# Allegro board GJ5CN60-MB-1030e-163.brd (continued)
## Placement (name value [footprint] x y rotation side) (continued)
C1069  -  [M-C0402]  43 104.73 270 bottom
C1070  -  [M-C0402]  42.37 90.12 0 top
C1071  -  [M-C0402]  56.34 140.16 90 bottom
C1072  -  [M-C0603]  45.87 72.65 180 bottom
C1073  -  [M-C0603]  46.58 74.73 180 bottom
C1074  -  [M-C0402]  35.89 90.12 180 top
C1075  -  [M-C0402]  33.98 90.12 180 top
C1076  -  [M-C0402]  29.16 98.25 270 top
C1077  -  [M-C0402]  29.16 100.16 270 top
C1078  -  [M-C0603]  28.9 102.57 90 top
C1128  -  [M-C0402]  72.47 104.22 180 bottom
C1137  -  [M-C0402]  76.4 101.43 180 bottom
C1138  -  [M-C0603]  83.98 98.66 90 bottom
C1139  -  [M-C0603]  22.94 85.55 0 bottom
C1144  -  [M-C0603]  81.21 98.66 90 bottom
C1151  -  [M-C0402]  70.69 104.22 180 bottom
C1152  -  [M-C0402]  70.69 102.82 180 bottom
C1153  -  [M-C0402]  96.67 96.83 180 bottom
C1161  -  [M-C0603]  78.24 98.61 90 bottom
C1163  -  [M-C0603]  75.44 98.59 270 bottom
C1164  -  [M-C0402]  72.47 101.43 180 bottom
C1165  -  [M-C0603]  22.94 86.95 0 bottom
C1167  -  [M-C0603]  73.95 98.66 90 bottom
C1169  -  [M-C0603]  82.61 98.59 270 bottom
C1170  -  [M-C0402]  183.69 153.11 0 top
C1176  -  [M-C0402]  126.47 156.11 90 top
C1179  -  [M-C0402]  18.87 147.53 180 top
C1180  -  [M-C0402]  18.87 149.05 180 top
C1181  -  [M-C0402]  87.07 113.36 0 bottom
C1182  -  [M-C0402]  76.4 102.82 180 bottom
C1183  -  [M-C0402]  79.7 105.62 180 bottom
C1184  -  [M-C0402]  86.82 106 90 bottom
C1185  -  [M-C0402]  18.11 122.51 180 top
C1186  -  [M-C0402]  70.69 101.43 180 bottom
C1187  -  [M-C0402]  97.66 111.59 90 bottom
C1188  -  [M-C0402]  72.47 102.82 180 bottom
C1189  -  [M-C0402]  74.04 89.61 0 bottom
C1190  -  [M-C0402]  92.4 110.06 90 bottom
C1191  -  [M-C0402]  82.12 95.84 180 bottom
C1192  -  [M-C0402]  85.93 95.84 0 bottom
C1193  -  [M-C0402]  117.68 156.04 90 top
C1194  -  [M-C0402]  133.88 155.5 90 top
C1195  -  [M-C0402]  141.83 156.01 90 top
C1196  -  [M-C0402]  152.12 150.78 90 top
C1197  -  [M-C0402]  161.11 150.78 90 top
C1216  -  [M-C0402]  133.06 155.37 90 top
C1217  -  [M-C0402]  140.56 155.37 90 top
C1218  -  [M-C0402]  87.73 93.69 0 bottom
C1219  -  [M-C0402]  148.77 155.5 90 top
C1220  -  [M-C0402]  125.34 155.58 90 top
C1221  -  [M-C0402]  159.46 150.24 90 top
C1222  -  [M-C0402]  168.6 150.32 90 top
C1223  -  [M-C0402]  105.99 101.43 180 bottom
C1224  -  [M-C0402]  105.99 98.25 180 bottom
C1225  -  [M-C0402]  108.03 100.28 180 bottom
C1226  -  [M-C0402]  108.03 99.39 180 bottom
C1227  -  [M-C0402]  105.99 99.14 180 bottom
C1234  -  [M-C0603]  16.71 61.67 90 top
C1235  -  [M-C0603]  32.07 57.18 0 top
C1236  -  [M-C0603]  184.76 112.33 90 top
C1237  -  [M-C0603]  185.04 103.94 270 top
C1243  -  [M-C0402]  87.72 89.39 180 bottom
C1244  -  [M-C0402]  68.43 94.87 90 bottom
C1245  -  [M-C0603]  73.98 95.08 270 bottom
C1246  -  [M-C0402]  80.09 95.84 0 bottom
C1247  -  [M-C0603]  5.41 72.09 0 top
C1248  -  [M-C0402]  85.93 93.04 0 bottom
C1249  -  [M-C0402]  84.15 93.04 0 bottom
C1250  -  [M-C0603]  75.43 95.08 270 bottom
C1251  -  [M-C0603]  96.21 111.59 90 bottom
C1252  -  [M-C0402]  78.05 89.61 180 bottom
C1253  -  [M-C0603]  93.92 111.59 90 bottom
C1254  -  [M-C0603]  91.26 109.81 90 bottom
C1255  -  [M-C0603]  89.91 107.67 90 bottom
C1256  -  [M-C0603]  41.86 143.46 180 bottom
C1257  -  [M-C0603]  72.57 98.59 270 bottom
C1258  -  [M-C0603]  3 68.41 90 top
C1259  -  [M-C0603]  5.16 65.1 180 top
C1260  -  [M-C0402]  94.06 113.36 180 bottom
C1261  -  [M-C0402]  81.72 91.63 0 bottom
C1262  -  [M-C0402]  82.12 93.04 180 bottom
C1263  -  [M-C0402]  96.21 113.36 0 bottom
C1264  -  [M-C0402]  80.96 107.66 180 bottom
C1265  -  [M-C0402]  82.74 107.66 0 bottom
C1266  -  [M-C0402]  77.93 105.62 0 bottom
C1267  -  [M-C0402]  70.05 105.62 0 bottom
C1268  -  [M-C0603]  76.77 98.66 90 bottom
C1269  -  [M-C0603]  88.87 112.73 270 bottom
C1270  -  [M-C0603]  183.59 8.72 0 top
C1271  -  [M-C0603]  183.59 7.32 0 top
C1272  -  [M-C0603]  178.76 9.6 180 top
C1273  -  [M-C0603]  81.19 102.17 90 bottom
C1274  -  [M-C0402]  85.07 89.58 180 bottom
C1275  -  [M-C0603]  41.86 136.35 180 bottom
C1276  -  [M-C0603]  188.29 18.88 0 bottom
C1277  -  [M-C0402]  81.23 104.22 0 bottom
C1278  -  [M-C0603]  188.29 20.27 0 bottom
C1279  -  [M-C0402]  71.83 105.62 0 bottom
C1280  -  [M-C0603]  188.29 17.48 0 bottom
C1281  -  [M-C0402]  85.55 105.62 180 bottom
C1282  -  [M-C0402]  68.77 101.55 180 bottom
C1283  -  [M-C0402]  69.42 107.65 0 bottom
C1284  -  [M-C0402]  75.89 107.65 0 bottom
C1285  -  [M-C0402]  86.31 91.65 180 bottom
C1286  -  [M-C0603]  70.61 98.59 90 bottom
C1287  -  [M-C0402]  68.91 102.71 180 bottom
C1288  -  [M-C0603]  79.82 98.59 270 bottom
C1289  -  [M-C0402]  83.64 105.62 180 bottom
C1290  -  [M-C0402]  9.98 88.73 270 bottom
C1291  -  [M-C0402]  75.89 105.62 0 bottom
C1292  -  [M-C0402]  70.15 91.6 0 bottom
C1293  -  [M-C0402]  129.44 159.52 0 top
C1294  -  [M-C0402]  136.75 159.01 0 top
C1295  -  [M-C0402]  89.51 96.98 270 bottom
C1296  -  [M-C0402]  90.24 100.67 0 bottom
C1297  -  [M-C0603]  4.16 88.6 270 bottom
C1298  -  [M-C0402]  76.4 91.65 180 bottom
C1299  -  [M-C0402]  73.71 91.6 180 bottom
C1300  -  [M-C0402]  144.91 159.46 0 top
C1301  -  [M-C0402]  121.23 159.46 0 top
C1302  -  [M-C0402]  90.25 98.68 0 bottom
C1303  -  [M-C0402]  86.35 89.16 90 bottom
C1304  -  [M-C0603]  2.74 88.6 270 bottom
C1305  -  [M-C0603]  8.71 88.6 270 bottom
C1306  -  [M-C0603]  7.06 88.57 270 bottom
C1307  -  [M-C0402]  162.13 154.56 180 top
C1308  -  [M-C0402]  155.27 154.13 0 top
C1309  -  [M-C0603]  66.24 86.95 45 bottom
C1310  -  [M-C0402]  6.93 154.89 270 top
C1311  -  [M-C0402]  6.88 141.18 90 top
C1312  -  [M-C0402]  17.98 129.49 270 bottom
C1313  -  [M-C0402]  74.12 105.62 0 bottom
C1314  -  [M-C0402]  128.85 154.26 0 top
C1315  -  [M-C0402]  193.83 98 0 top
C1316  -  [M-C0402]  136.22 153.75 0 top
C1317  -  [M-C0402]  144.35 154 0 top
C1318  -  [M-C0402]  140.54 28.15 90 top
C1319  -  [M-C0603]  139.39 27.89 90 top
C1320  -  [M-C0603]  85.29 109.73 180 bottom
C1321  -  [M-C0402]  159.46 28.65 90 top
C1322  -  [M-C0402]  158.57 28.65 90 top
C1323  -  [M-C0402]  120.6 154.13 0 top
C1324  -  [M-C0402]  154.76 148.67 0 top
C1325  -  [M-C0402]  163.52 148.67 0 top
C1326  -  [M-C0402]  164.29 28.15 90 top
C1327  -  [M-C0603]  165.43 27.89 90 top
C1328  -  [M-C0402]  180.8 28.02 90 top
C1329  -  [M-C0402]  179.91 28.02 90 top
C1330  -  [M-C0402]  80.09 94.44 0 bottom
C1331  -  [M-C0402]  75.25 92.92 180 bottom
C1332  -  [M-C0402]  84.15 94.44 0 bottom
C1333  -  [M-C0402]  73.47 92.92 180 bottom
C1334  -  [M-C0402]  74.24 101.43 0 bottom
C1335  -  [M-C0402]  82.12 94.44 180 bottom
C1336  -  [M-C0402]  81.48 105.62 0 bottom
C1337  -  [M-C0402]  84.15 95.84 0 bottom
C1338  -  [M-C0402]  85.93 94.44 0 bottom
C1339  -  [M-C0402]  79.99 91.61 0 bottom
C1340  -  [M-C0402]  79.87 89.62 0 bottom
C1341  -  [M-C0402]  70.31 89.61 0 bottom
C1342  -  [M-C0402]  83.77 91.65 180 bottom
C1343  -  [M-C0603]  67.77 109.05 135 bottom
C1344  -  [M-C0603]  22.88 84.23 0 bottom
C1345  -  [M-C0603]  22.91 82.86 0 bottom
C1346  -  [M-C0603]  80.52 85.3 180 bottom
C1347  -  [M-C0402]  67.44 159.85 90 top
C1348  -  [M-C0603]  89.1 122 180 bottom
C1349  -  [M-C0402]  183.64 69.22 0 bottom
C1350  -  [M-C0603]  28.9 84.99 270 top
C1351  -  [M-C0603]  26.24 93.68 90 top
C1352  -  [M-C0603]  23.44 93.68 90 top
C1353  -  [M-C0603]  24.84 93.68 90 top
C1354  -  [M-C0603]  40.97 67.14 0 bottom
C1355  -  [M-C0603]  87.96 106 270 bottom
C1356  -  [M-C0603]  86.05 98.66 90 bottom
C1357  -  [M-C0603]  40.97 68.66 0 bottom
C1358  -  [M-C0603]  178.76 9.6 180 bottom
C1361  -  [M-C0402]  19.89 74.25 270 bottom
C1362  -  [M-C0402]  19.86 120.09 270 top
C1363  -  [M-C0603]  2.23 79.71 180 bottom
C1364  -  [M-C0402]  20.27 67.64 180 bottom
C1367  -  [M-C0402]  13.16 65.03 180 top
C1368  -  [M-C0402]  24.33 105.49 0 top
C1369  -  [M-C0805]  84.02 53.42 270 top
C1370  -  [M-C0603]  83.39 72.09 180 top
C1371  -  [M-C0402]  13.79 105.11 0 top
C1372  -  [M-C0805]  161.87 137.21 0 top
C1373  -  [M-C0805]  161.87 135.18 0 top
C1374  -  [M-C0402]  93.04 62.06 180 top
C1375  -  [M-C0402]  79.7 55.32 180 top
C1376  -  [M-C0805]  152.35 137.87 180 top
C1377  -  [M-C0805]  152.35 135.84 180 top
C1378  -  [M-C0603]  5.61 88.6 270 bottom
C1382  -  [M-C0402]  74.12 107.65 0 bottom
C1383  -  [M-C0402]  76.4 104.22 180 bottom
C1384  -  [M-C0402]  83.01 104.22 0 bottom
C1385  -  [M-C0603]  2.23 81.11 180 bottom
C1386  -  [M-C0402]  74.24 104.22 0 bottom
C1387  -  [M-C0402]  75.38 89.11 270 bottom
C1388  -  [M-C0402]  77.21 108.08 90 bottom
C1389  -  [M-C0402]  74.24 102.82 0 bottom
C1390  -  [M-C0402]  78.17 91.63 180 bottom
C1391  -  [M-C0603]  92.15 128.73 90 bottom
C1392  -  [M-C0402]  68.81 96.19 180 bottom
C1393  -  [M-C0402]  71.96 108.08 90 bottom
C1394  -  [M-C0402]  78.03 108.06 270 bottom
C1395  -  [M-C0402]  80.96 108.55 180 bottom
C1396  -  [M-C0402]  84.15 108.03 270 bottom
C1397  -  [M-C0402]  70.43 88.73 0 bottom
C1398  -  [M-C0402]  72.85 108.08 90 bottom
C1399  -  [M-C0402]  74.12 108.54 180 bottom
C1400  -  [M-C0402]  76.27 89.11 270 bottom
C1401  -  [M-C0402]  95.07 111.33 90 bottom
C1402  -  [M-C0402]  71.93 91.6 0 bottom
C1403  -  [M-C0402]  68.66 104.47 0 bottom
C1404  -  [M-C0402]  81.17 89.14 270 bottom
C1405  -  [M-C0402]  68.85 103.58 180 bottom
C1406  -  [M-C0402]  68.66 93.55 180 bottom
C1407  -  [M-C0402]  68.91 97.92 180 bottom
C1408  -  [M-C0402]  78.87 108.06 90 bottom
C1409  -  [M-C0402]  71.83 89.13 270 bottom
C1410  -  [M-C0402]  68.81 98.78 0 bottom
C1411  -  [M-C0402]  68.81 97.06 180 bottom
C1412  -  [M-C0402]  68.77 100.66 180 bottom
C1413  -  [M-C0402]  88.09 88.09 90 bottom
C1414  -  [M-C0603]  6.04 79.33 270 bottom
C1415  -  [M-C0402]  86.69 86.82 90 bottom
C1416  -  [M-C0402]  79.87 88.73 0 bottom
C1417  -  [M-C0402]  87.83 99.67 0 bottom
C1418  -  [M-C0402]  99.77 83.77 90 top
C1419  -  [M-C0402]  99.77 85.68 270 top
C1420  -  [M-C7343]  82.06 102.65 180 bottom
C1421  -  [M-C0402]  75.89 108.54 0 bottom
C1422  -  [M-C0402]  79.7 108.05 90 bottom
C1423  -  [M-C0603]  61.34 57.99 0 top
C1424  -  [M-C7343]  74.46 94.63 0 bottom
C1425  -  [M-C0603]  68.58 58.25 270 top
C1426  -  [M-C0402]  82.63 58.75 180 top
C1427  -  [M-C0402]  72.97 47.7 90 top
C1428  -  [M-C7343]  42.37 68.15 0 top
C1429  -  [M-C0603]  7.44 79.33 270 bottom
C1431  -  [M-C0603]  22.94 78.06 0 bottom
C1432  -  [M-C0402]  71.07 108.08 90 bottom
C1433  -  [M-C0402]  87.75 96.53 0 bottom
C1434  -  [M-C0603]  2.11 79.71 180 top
C1435  -  [M-C7343]  38.05 159.72 90 top
C1436  -  [M-C7343]  33.5 159.69 90 top
C1437  -  [M-C7343]  26.11 76.15 90 top
C1438  -  [M-C0805]  83.26 70.31 180 top
C1439  -  [M-C7343]  31.06 138.59 180 bottom
C1440  -  [M-C0603]  69.59 62.94 90 top
C1441  -  [M-C0603]  67.18 58.25 270 top
C1442  -  [M-C0402]  90.4 87.76 90 bottom
C1443  -  [M-C0402]  89.51 87.76 90 bottom
C1444  -  [M-C0402]  77.67 88.73 0 bottom
C1445  -  [M-C0402]  84.4 77.04 180 top
C1446  -  [M-C0402]  90.63 90.12 180 bottom
C1447  -  [M-C0603]  4.27 82.12 90 bottom
C1448  -  [M-C0603]  5.79 154.89 270 top
C1449  -  [M-C7343]  31.06 147.53 180 bottom
C1450  -  [M-C0603]  2.11 81.11 180 top
C1451  -  [M-C0402]  88.09 91.93 0 bottom
C1452  -  [M-C0402]  107.26 72.98 180 top
C1453  -  [M-C7343]  31.06 134.19 180 bottom
C1454  -  [M-C0603]  2.36 140.54 180 top
C1455  -  [M-C0603]  4.32 141.13 90 top
C1456  -  [M-C0402]  87.71 92.79 0 bottom
C1457  -  [M-C0402]  87.75 97.42 0 bottom
C1458  -  [M-C0402]  87.83 90.25 0 bottom
C1459  -  [M-C7343]  31.06 143.08 180 bottom
C1463  -  [M-C0603]  5.74 141.18 90 top
C1464  -  [M-C0603]  12.62 161.37 90 top
C1465  -  [M-C0603]  14.05 161.37 90 top
C1466  -  [M-C0603]  15.47 161.37 90 top
C1467  -  [M-C0603]  16.84 129.24 270 bottom
C1468  -  [M-C0603]  6.04 127.84 180 top
C1469  -  [M-C7343]  25.35 134.83 180 top
C1470  -  [M-C0603]  11.23 161.37 90 top
C1471  -  [M-C0603]  2.36 139.14 180 top
C1472  -  [M-C0603]  4.14 158.83 180 top
C1476  -  [M-C0402]  113.24 124.03 180 top
C1477  -  [M-C0402]  115.15 122.99 180 top
C1478  -  [M-C0402]  113.23 121.95 180 top
C1479  -  [M-C0402]  115.14 120.91 180 top
C1480  -  [M-C0402]  113.22 119.78 180 top
C1481  -  [M-C0402]  115.14 118.75 180 top
C1482  -  [M-C0402]  113.23 117.68 180 top
C1483  -  [M-C0402]  115.14 116.64 180 top
C1488  -  [M-C0402]  113.23 114.71 180 top
C1489  -  [M-C0402]  115.14 114.51 180 top
C1490  -  [M-C0402]  113.23 113.49 180 top
C1491  -  [M-C0402]  115.14 112.4 180 top
C1492  -  [M-C0402]  113.23 123.14 180 top
C1493  -  [M-C0402]  115.15 122.1 180 top
C1494  -  [M-C0402]  113.23 121.06 180 top
C1495  -  [M-C0402]  115.14 120.02 180 top
C1496  -  [M-C0402]  113.22 118.92 180 top
C1497  -  [M-C0402]  115.14 117.86 180 top
C1498  -  [M-C0402]  113.23 116.79 180 top
C1499  -  [M-C0402]  115.14 115.75 180 top
C1504  -  [M-C0402]  113.23 115.6 180 top
C1505  -  [M-C0402]  115.14 113.62 180 top
C1506  -  [M-C0402]  113.23 112.6 180 top
C1507  -  [M-C0402]  115.14 111.51 180 top
C1508  -  [M-C0402]  175.98 12.69 0 top
C1509  -  [M-C0402]  113.23 110.44 180 top
C1510  -  [M-C0402]  113.23 111.33 180 top
C1511  -  [M-C0402]  115.14 109.43 180 top
C1512  -  [M-C0402]  115.14 110.32 180 top
C1513  -  [M-C0402]  113.23 109.15 180 top
C1514  -  [M-C0402]  113.23 108.26 180 top
C1515  -  [M-C0402]  115.14 107.29 180 top
C1516  -  [M-C0402]  115.14 108.18 180 top
C2396  -  [M-C0603]  6.04 129.24 180 top
C2397  -  [M-C0603]  15.44 129.24 270 bottom
C2398  -  [M-C0603]  4.14 157.43 180 top
C2549  -  [M-C0402]  23.57 111.08 270 top
C2550  -  [M-C0402]  20.01 111.08 90 top
C2551  -  [M-C0402]  16.84 72.22 270 top
C2552  -  [M-C0402]  24.08 109.68 180 top
C2553  -  [M-C0402]  21.64 109.68 180 top
C2554  -  [M-C0402]  14.98 70.69 270 bottom
C2555  -  [M-C0402]  16.33 69.17 0 bottom
C2575  -  [M-C0402]  78.05 157.31 270 bottom
C2578  -  [M-C0402]  69.8 156.8 180 bottom
C2579  -  [M-C0402]  69.8 155.53 180 bottom
C2745  -  [M-C0402]  170.51 12.91 90 top
C2746  -  [M-C0402]  112.09 5.54 90 bottom
C2747  -  [M-C0402]  98.12 4.78 90 bottom
C2821  -  [M-C0402]  18.36 108.92 270 top
C3384  -  [M-C0402]  167.69 24.18 90 top
C3399  -  [M-C0402]  111.45 88.73 270 bottom
C3401  -  [M-C0402]  113.49 76.79 0 bottom
C3416  -  [M-C0402]  124.79 75.52 0 bottom
C3417  -  [M-C0402]  140.92 68.28 90 bottom
C3418  -  [M-C0402]  142.32 68.28 90 bottom
C3419  -  [M-C0402]  146 68.28 90 bottom
C3420  -  [M-C0402]  147.01 68.28 90 bottom
C3421  -  [M-C0603]  118.06 80.85 90 bottom
C3422  -  [M-C0402]  141.43 81.49 90 bottom
C3423  -  [M-C0402]  151.21 77.04 0 bottom
C3424  -  [M-C0402]  115.14 80.98 90 bottom
C3425  -  [M-C0402]  151.84 68.28 90 bottom
C3426  -  [M-C0603]  110.31 88.98 270 bottom
C3427  -  [M-C0603]  141.68 91.77 90 top
C3428  -  [M-C0603]  146.13 91.77 90 top
C3431  -  [M-C0603]  152.35 91.77 90 top
C3432  -  [M-C0603]  144.52 91.77 90 top
C3438  -  [M-C0603]  145.74 77.04 180 bottom
C3439  -  [M-C0603]  169.75 76.28 90 bottom
C3440  -  [M-C0603]  154.38 77.04 0 bottom
C3441  -  [M-C0603]  125.04 76.79 0 bottom
C3443  -  [M-C0603]  118.69 67.52 90 bottom
C3445  -  [M-C0402]  117.55 67.9 90 bottom
C3447  -  [M-C0603]  113.11 68.66 180 bottom
C3463  -  [M-C0402]  162.64 91.9 270 top
C3464  -  [M-C0402]  173.3 91.9 270 top
C3465  -  [M-C0402]  154.12 91.76 270 top
C3466  -  [M-C0402]  127.18 90.99 0 top
C3467  -  [M-C0402]  138.51 92.03 270 top
C3468  -  [M-C0402]  140.03 92.03 270 top
C3470  -  [M-C0402]  149.05 91.77 90 top
C3471  -  [M-C0402]  143.18 91.9 90 top
C3491  -  [M-C0402]  80.01 6.58 90 top
C3493  -  [M-C0402]  80.9 6.61 90 top
C3495  -  [M-C0402]  97.36 7.57 0 top
C3496  -  [M-C0603]  96.85 8.21 0 bottom
C3532  -  [M-C0402]  63.14 36.33 0 top
C3535  -  [M-C0402]  63.58 34.98 90 top
C3536  -  [M-C0402]  62.66 34.95 270 top
C3537  -  [M-C0402]  69.93 39.2 180 top
C3538  -  [M-C0603]  6.02 39.53 270 top
C3539  -  [M-C0603]  45.16 62.31 90 bottom
C3540  -  [M-C0603]  3.15 39.6 270 top
C3541  -  [M-C0402]  60.65 40.59 0 top
C3543  -  [M-C0402]  52.91 56.98 0 top
C3544  -  [M-C0603]  45.03 52.66 0 bottom
C3545  -  [M-C0603]  16.84 45.29 90 top
C3546  -  [M-C0603]  45.03 54.05 0 bottom
C3547  -  [M-C0603]  45.03 51.23 0 bottom
C3548  -  [M-C0603]  27.38 42.12 0 top
C3549  -  [M-C0402]  39.95 39.58 270 bottom
C3550  -  [M-C0402]  43.13 39.58 270 bottom
C3551  -  [M-C0402]  28.02 38.05 270 top
C3552  -  [M-C0402]  37.79 39.58 270 bottom
C3553  -  [M-C0402]  41.22 39.58 270 bottom
C3554  -  [M-C0603]  4.57 39.58 270 top
C3556  -  [M-C0402]  65.28 36.27 180 top
C3557  -  [M-C0402]  69.93 40.08 180 top
C3558  -  [M-C0402]  27.13 45.67 0 top
C3559  -  [M-C0402]  61.54 46.82 0 top
C3560  -  [M-C0402]  66.75 46.18 90 top
C3561  -  [M-C0603]  183.46 99.14 90 top
C3562  -  [M-C0603]  184.86 99.14 90 top
C3563  -  [M-C0603]  186.26 99.14 90 top
C3564  -  [M-C0402]  15.19 45.42 90 top
C3565  -  [M-C0402]  69.93 41.23 180 top
C3566  -  [M-C0603]  192.1 69.68 0 top
C3567  -  [M-C0603]  192.1 71.2 0 top
C3568  -  [M-C0603]  192.1 74.25 0 top
C3569  -  [M-C0603]  192.1 72.72 0 top
C3570  -  [M-C0603]  188.29 16.08 0 bottom
C3571  -  [M-C0603]  129.56 160.66 0 top
C3572  -  [M-C0603]  59.89 39.45 0 top
C3573  -  [M-C0603]  46.56 62.31 270 bottom
C3574  -  [M-C0402]  63.58 45.04 180 top
C3575  -  [M-C0603]  40.33 44.4 0 bottom
C3576  -  [M-C0402]  61.04 44.53 90 top
C3577  -  [M-C0603]  40.33 45.93 0 bottom
C3578  -  [M-C0603]  41.48 172.16 0 top
C3579  -  [M-C0402]  60.65 42.37 180 top
C3580  -  [M-C0402]  61.92 44.53 90 top
C3581  -  [M-C0402]  51 62.06 270 top
C3582  -  [M-C0402]  69.16 35.89 180 top
C3583  -  [M-C0402]  67.77 37.67 90 top
C3584  -  [M-C0603]  129.56 162.11 0 bottom
C3585  -  [M-C0603]  129.56 163.53 0 top
C3586  -  [M-C0603]  129.56 162.11 0 top
C3587  -  [M-C0603]  129.56 163.53 0 bottom
C3588  -  [M-C0603]  136.93 160.23 0 top
C3589  -  [M-C0603]  136.93 161.65 0 top
C3590  -  [M-C0603]  136.93 160.23 0 bottom
C3591  -  [M-C0603]  136.93 161.65 0 bottom
C3592  -  [M-C0603]  136.93 163.05 0 top
C3593  -  [M-C0603]  182.07 99.14 90 top
C3594  -  [M-C0603]  145.08 160.63 0 top
C3595  -  [M-C0603]  145.08 162.06 0 top
C3596  -  [M-C0603]  145.08 163.48 0 top
C3597  -  [M-C0603]  145.08 160.63 0 bottom
C3598  -  [M-C0603]  145.08 162.06 0 bottom
C3599  -  [M-C0603]  121.36 160.61 0 bottom
C3600  -  [M-C0603]  83.9 42.5 270 top
C3601  -  [M-C0603]  82.5 42.5 270 top
C3602  -  [M-C0603]  81.1 42.5 270 top
C3603  -  [M-C0402]  91.52 41.23 180 top
C3604  -  [M-C0402]  85.55 47.32 270 top
C3605  -  [M-C0603]  121.36 162 0 bottom
C3606  -  [M-C0603]  96.21 40.97 90 top
C3607  -  [M-C0603]  121.36 163.4 0 top
C3608  -  [M-C0603]  121.39 162 0 top
C3609  -  [M-C0603]  121.36 160.61 0 top
C3610  -  [M-C0603]  155.19 155.27 0 bottom
C3611  -  [M-C0603]  99.01 40.97 90 top
C3612  -  [M-C0603]  97.61 40.97 90 top
C3613  -  [M-C0603]  94.82 40.97 90 top
C3614  -  [M-C0603]  155.19 156.64 0 top
C3615  -  [M-C0603]  155.19 156.67 0 bottom
C3616  -  [M-C0402]  172.29 61.55 270 bottom
C3617  -  [M-C0402]  173.3 61.55 270 bottom
C3618  -  [M-C0603]  155.19 158.07 0 bottom
C3619  -  [M-C0603]  155.19 155.25 0 top
C3620  -  [M-C0402]  167.57 15.14 0 bottom
C3621  -  [M-C0402]  167.57 16.03 0 bottom
C3622  -  [M-C0402]  171.78 18.24 270 bottom
C3623  -  [M-C0402]  111.28 125.73 180 bottom
C3624  -  [M-C0603]  162.05 155.65 180 top
C3625  -  [M-C0402]  117.68 125.56 180 bottom
C3626  -  [M-C0402]  112.6 123.02 0 bottom
C3627  -  [M-C0402]  119.96 124.54 180 bottom
C3628  -  [M-C0603]  79.7 42.5 270 top
C3629  -  [M-C0603]  165.99 157.76 0 top
C3630  -  [M-C0402]  174.83 56.09 180 bottom
C3631  -  [M-C0402]  171.53 16.08 270 top
C3632  -  [M-C0603]  111.17 154.54 0 top
C3633  -  [M-C0805]  95.33 158.32 270 top
C3634  -  [M-C0402]  113.46 125.12 180 top
C3635  -  [M-C0402]  75.13 57.86 90 top
C3636  -  [M-C0603]  165.99 159.13 0 top
C3637  -  [M-C0603]  165.99 156.39 0 top
C3638  -  [M-C0402]  97.1 160.1 270 bottom
C3641  -  [M-C0402]  117.68 124.29 0 bottom
C3642  -  [M-C0603]  141.68 172.29 180 top
C3643  -  [M-C0402]  117.68 123.4 0 bottom
C3644  -  [M-C0402]  117.68 126.44 0 bottom
C3645  -  [M-C0402]  103.25 157.81 270 top
C3646  -  [M-C0402]  117.68 127.33 0 bottom
C3647  -  [M-C0603]  176.48 59.13 270 bottom
C3648  -  [M-C0603]  175.08 59.13 270 bottom
C3649  -  [M-C0603]  170.26 59.01 270 bottom
C3650  -  [M-C0402]  193.8 97.11 180 top
C3651  -  [M-C0603]  168.86 59.01 270 bottom
C3652  -  [M-C0603]  170.13 18.11 0 bottom
C3653  -  [M-C0603]  170.13 19.51 0 bottom
C3654  -  [M-C0603]  166.57 13.29 180 top
C3655  -  [M-C0603]  166.57 14.68 180 top
C3656  -  [M-C0603]  71.58 63.45 180 top
C3657  -  [M-C0603]  71.58 64.85 180 top
C3658  -  [M-C0603]  81.61 63.15 0 top
C3659  -  [M-C0603]  81.53 64.49 0 top
C3660  -  [M-C0603]  95.91 158.37 270 bottom
C3661  -  [M-C0603]  94.54 158.37 270 bottom
C3669  -  [M-C0402]  96.21 162.77 270 top
C3742  -  [M-C0402]  100.28 162.77 270 top
C3743  -  [M-C0402]  103.07 161.12 180 top
C3744  -  [M-C0603]  111.17 153.14 0 top
C3745  -  [M-C0603]  111.17 151.62 0 top
C3747  -  [M-C0603]  111.17 150.02 0 top
C3847  -  [M-C0402]  7.57 65.1 180 top
C3892  -  [M-C0402]  77.29 61.04 90 top
C3893  -  [M-C0402]  74.37 64.72 270 top
C3895  -  [M-C0402]  72.74 60.91 270 top
C3896  -  [M-C0402]  75.64 64.72 270 top
C3897  -  [M-C0805]  191.39 51.74 0 bottom
C3898  -  [M-C0603]  189.31 53.55 180 bottom
C3899  -  [M-C0805]  188.09 51.72 180 bottom
C3901  -  [M-C0402]  145.49 5.67 90 bottom
C3902  -  [M-C0402]  98.25 2.87 90 bottom
C3903  -  [M-C0402]  158.32 3.76 90 bottom
C3904  -  [M-C0402]  96.34 1.73 180 bottom
C3912  -  [M-C0402]  73.61 57.99 180 top
C3913  -  [M-C0402]  76.53 58.37 0 top
C3939  -  [M-C0402]  17.86 150.07 180 top
C3940  -  [M-C0402]  7.95 146.13 180 top
C3941  -  [M-C0402]  16.33 120.09 180 top
C3962  -  [M-C0805]  116.43 171.53 90 top
C3988  -  [M-C0402]  30.3 153.62 270 bottom
C3989  -  [M-C0402]  183.97 165.31 270 top
C3990  -  [M-C0603]  13.54 64.8 0 bottom
C3991  -  [M-C0603]  13.51 63.43 0 bottom
C3992  -  [M-C0603]  11.25 65.36 90 bottom
C4078  -  [M-C0805]  128.35 170.89 270 bottom
C4079  -  [M-C0805]  125.81 170.13 0 top
C4084  -  [M-C0402]  95.2 4.14 270 bottom
C4085  -  [M-C0603]  94.06 3.89 270 bottom
C4092  -  [M-C0402]  93.78 167.11 0 bottom
C4093  -  [M-C0603]  93.98 168.23 0 bottom
C4094  -  [M-C0402]  91.52 156.42 0 bottom
C4102  -  [M-C0402]  106.25 171.78 180 top
C4103  -  [M-C0402]  106.25 172.67 180 top
C4104  -  [M-C0805]  136.73 170.49 90 top
C4105  -  [M-C0805]  109.93 172.16 0 bottom
C4106  -  [M-C0805]  106.63 168.35 180 top
C4107  -  [M-C0805]  106.63 168.35 180 bottom
C4108  -  [M-C0805]  109.93 170.13 0 bottom
C4109  -  [M-C0805]  106.63 170.39 180 top
C4110  -  [M-C0805]  106.63 170.39 180 bottom
C4114  -  [M-C0402]  174.95 156.92 90 top
C4115  -  [M-C0402]  176.73 159.34 270 top
C4117  VALUE  [CAP_EEEFZ1E101P_6D3_L45]  179.78 94.31 90 top
C4118  VALUE  [CAP_EEEFZ1E101P_6D3_L60]  115.09 163.3 90 top
C4119  VALUE  [CAP_EEEFZ1E101P_6D3_L60]  151.1 167.64 270 top
C4120  VALUE  [CAP_EEEFZ1E101P_6D3_L60]  4.52 134.45 180 top
C4121  VALUE  [CAP_EEEFZ1E101P_6D3_L45]  4.95 95.89 0 top
CN1  value  [CON_S-DDR4-S80_D4ASX-260-80_ARG]  114.39 81.1 0 top
CN4  VALUE*  [CON_WB_2H125_W-00-1025_JCTC]  182 29.91 180 bottom
CN9  -  [CON_WB_10H08_50208-010_ACES]  165.4 4.11 0 top
CN11  value  [CON_S-DDR4-S40_D4ASX-260-40_ARG]  114.39 68.2 0 top
CN12  VALUE  [CON_FFC_50B05_FP225H050S10M_JXT]  9 61.61 90 bottom
CN14  -  [CON_WB_10H08_50208-010_ACES]  187.6 57.99 0 bottom
CN17  Value*  [CON_FFC_10R05_6712K-V10N07L_ENT]  107.6 4 0 top
CN18  VALUE*  [CON_FFC_6R100_51524-00601_ACES]  153.1 7.25 0 top
CN19  VALUE  [CON_FFC_6R05-AFC34-S06FCA_HF]  96.42 4.5 0 top
CN23  -  [CON_SUSB_3SR_UEA1111-R04012_FOX]  131.13 176.55 180 top
CN26  Value*  [CON_HDMI-A-R_HAR01-191CN5V_HT]  64.8 178.85 180 top
CN30  -  [CON_WB_13V150_51481-01371_ACES]  40.97 44.91 0 top
CN32  -  [CON_SUSB_3SR_UEA1111-R04012_FOX]  111.03 176.55 180 top
CN34  val  [CON_RJ45_WO_130456-781_SANTA]  87.3 175.97 180 top
CN41  VALUE  [CON_FFC_6R05-AFC34-S06FCA_HF]  83.26 163.15 270 bottom
CN42  VALUE  [CON_FFC_6R05-AFC34-S06FCA_HF]  175.67 6.62 0 top
CNDCIN1  -  [CON_DCIN_WO_2DC3003-002211_SIN]  48.28 169.37 0 top
CNDEG1  -  [CON_WB_10H08_50208-010_ACES]  176.73 2.11 180 bottom
CNDEG2  VALUE*  [CON_WB_6H08_88460-0601_ACES]  141.68 3.89 0 top
CNEDP1  value  [CON_FFC_40R05-51517_ACES]  66.55 164.22 0 bottom
CNFAN1  Value*  [CON_WB_3H125_3800K-F03N_ENT]  11.1 149.36 180 bottom
CNFAN2  Value*  [CON_WB_3H125_3800K-F03N_ENT]  163.57 149.47 270 bottom
CNHDD1  -  [CON_FFC_18B05_51625-01801_ACES]  186.18 82.49 270 bottom
CNKB1  VALUE  [CON_FFC_40TB05_6718K_Y40N_ENT]  124.51 2.05 0 top
CNSSD1  VALUE  [CON_M2_M_S67_NXSM0-S67XX_ARG]  148.57 34.46 0 top
CNSSD2  VALUE  [CON_M2_M_S67_NXSM0-S67XX_ARG]  171.57 34.46 0 top
CNWLAN1  -  [CON_M2-E-S67_AS0BC21-S48BE_FOX]  89.2 13.25 0 top
CON3  val  [CON_SUSB-CS_UT11123-101W0_FXCN]  151.31 182.45 180 top
D1  -  [M-SOT23]  181.25 24.59 90 top
D3  -  [M-SOT23]  139.27 9.22 180 top
D4  -  [M-SOT23]  73.86 55.58 0 top
D10  -  [M-SOT23]  57.48 172.8 0 top
D16  -  [M-SOT23]  8.33 109.81 90 top
D23  -  [M-SOD323]  90.5 71.71 270 top
D24  -  [M-SOD323]  88.98 71.71 270 top
D26  -  [M-SOD323]  78.56 47.58 270 top
D27  -  [M-SOD323]  76.4 55.2 90 top
D28  -  [M-SOT23]  60.4 36.91 0 top
D29  -  [M-SOD323]  136.22 11.38 270 top
D30  -  [M-SOD323]  165.56 16.72 90 bottom
D37  -  [DIODE-AZ5315-02F]  131 173.32 180 top
D38  -  [DIODE-AZ5315-02F]  133.16 173.32 180 top
D39  -  [DIODE-AZ5315-02F]  128.59 173.32 180 top
D41  -  [M-SOT23]  57.35 166.2 0 top
D42  -  [DIODE-AZ5315-02F]  39.06 40.08 0 bottom
D43  -  [DIODE-AZ5315-02F]  42.11 40.08 0 bottom
D44  VALUE  [DIODE-AZ5315-02F]  73.1 156.54 180 bottom
D45  VALUE  [DIODE-AZ5315-02F]  75.03 156.54 180 bottom
D51  -  [M-SOT23]  75.13 45.93 0 top
D52  -  [M-SOT23]  79.32 52.15 180 top
D59  -  [DIODE-AZ5315-02F]  62.31 174.7 0 top
D60  -  [DIODE-AZ5315-02F]  113.99 172.93 180 top
D61  -  [DIODE-AZ5315-02F]  112.09 172.93 180 top
D62  -  [DIODE-AZ5315-02F]  109.68 172.93 180 top
ESD1  -  [DFN10_0D5_2D5X1D0]  150.95 178.21 180 top
ESD2  -  [DFN10_0D5_2D5X1D0]  153.87 178.21 0 top
ESD3  -  [DFN10_0D5_2D5X1D0]  148.44 179.2 0 bottom
G1  -  [BGA_2152_P070_375X375]  78.3 98.63 90 top
H2  -  [HOLEC276D118]  51.8 180.3 0 top
H3  @gi_h3  [GI_H3]  100.3 170.5 0 top
H4  -  [HOLEC276D118]  142.58 180.3 0 top
H5  @c315d110  [C315D110]  2.3 146.5 0 top
H6  @c315d110  [C315D110]  74.8 71.5 0 top
H7  @c315d110  [C315D110]  88.8 25 0 top
H8  @gi_h8  [GI_H8]  189.78 25 0 top
H12  @gi_h12  [GI_H12]  189.78 128.5 0 top
H13  -  [HOLEC295D157]  181.22 120.57 180 bottom
H14  -  [HOLEC295D157]  121.6 138.48 180 bottom
H15  -  [HOLEC295D157]  100.82 133.79 180 bottom
H16  SCRR223022-1C35  [C236D158]  49.1 161.57 180 bottom
H18  -  [HOLEC295D157]  18.27 95.79 180 bottom
H19  -  [HOLEC295D157]  121.62 97.66 0 top
H20  -  [HOLEC295D157]  100.82 66.99 0 top
H23  @c197d79  [C197D79]  27.12 176.8 0 top
H24  -  [HOLEC197D71]  159.54 181.3 0 top
H25  @c315d110  [C315D110]  16.8 34.5 0 top
JP1  -  [TOPOPEN_20X30]  172.64 22 270 top
JP2  -  [TOPOPEN_20X30]  173.68 23.7 270 top
L3  VALUE  [CHOKE_7D6X6D8_4]  24.46 127.08 0 top
L10  VALUE  [CHOKE_7D6X6D8_4]  24.46 142.45 0 top
L11  VALUE  [CHOKE_7D6X6D8_4]  24.59 154.13 0 top
L12  -  [CHOKE-7D3_8D3_5]  127.96 147.88 0 top
L13  -  [CHOKE-7D3_6D8_3]  179.56 108.88 270 top
L14  -  [CHOKE-7D3_8D3_5]  136.47 147.88 0 top
L15  -  [CHOKE-7D3_8D3_5]  144.98 147.91 0 top
L16  -  [CHOKE-4P_2X1_2X1_2]  77.67 155.27 0 bottom
L17  -  [CHOKE-7D3_8D3_5]  119.46 147.91 0 top
L20  -  [CHOKE-7D3_6D8_3]  156.02 143.47 0 top
L21  -  [CHOKE-7D3_6D8_3]  164.15 143.47 0 top
L22  -  [CHOKE-4P_2X1_2X1_2]  131 171.03 270 top
L23  -  [CHOKE-4P_2X1_2X1_2]  133.16 171.03 270 top
L24  -  [CHOKE-4P_2X1_2X1_2]  69.09 172.93 90 top
L25  -  [CHOKE-4P_2X1_2X1_2]  64.02 172.93 90 top
L26  -  [CHOKE-4P_2X1_2X1_2]  66.56 172.93 90 top
L27  -  [CHOKE-4P_2X1_2X1_2]  71.58 172.93 90 top
L28  VALUE  [CHOKE_7D6X6D8_4]  19.38 78.11 0 top
L29  -  [CHOKE-4P_2X1_2X1_2]  128.59 171.03 270 top
L34  -  [CHOKE-4P_2X1_2X1_2]  149.35 176.2 270 bottom
L35  -  [CHOKE-7D3_6D8_3]  189.2 12.57 90 top
L36  -  [CHOKE-4P_2X1_2X1_2]  151.28 174.81 270 top
L37  -  [CHOKE-4P_2X1_2X1_2]  154.81 174.81 270 top
L38  -  [CHOKE-4P_2X1_2X1_2]  149.5 174.81 270 top
L43  VALUE  [CHOKE_7D6X6D8_4]  19.38 86.11 0 top
L44  -  [CHOKE-4P_2X1_2X1_2]  147.5 176.2 270 bottom
L45  -  [CHOKE-4P_2X1_2X1_2]  153.06 174.81 270 top
L46  -  [CHOKE-4D1_4D0_2D0]  86.82 62.82 270 top
L48  -  [CHOKE-4P_2X1_2X1_2]  154 9.73 90 top
L49  -  [CHOKE-4D1_4D0_2D0]  45.8 54.94 180 top
L50  -  [CHOKE-7D3_6D8_3]  190.32 83.65 0 top
L51  -  [CHOKE-4P_2X1_2X1_2]  150.95 11.64 90 top
L52  -  [CHOKE_3X3_1D7]  66.8 61.17 270 top
L53  -  [CHOKE-7D3_6D8_3]  91.01 36.02 90 top
L54  -  [CHOKE_3X3_1D5]  101.29 47.07 270 top
L62  -  [CHOKE-4D1_4D0_2D0]  107.09 155.68 90 top
L65  -  [CHOKE-4P_2X1_2X1_2]  111.96 170.77 270 top
L66  -  [CHOKE-4P_2X1_2X1_2]  109.55 170.77 270 top
L67  -  [CHOKE-4P_2X1_2X1_2]  113.99 170.77 270 top
LED1  -  [LED_19-223-R7G]  175.61 161.6 90 bottom
LED2  -  [LED_WHITE_4_RNM_RNM]  158.5 170.19 90 bottom
LED4  -  [LED_WHITE_4_RNM_RNM]  21.57 161.53 90 bottom
LT2  -  [GST5009]  85.65 167.11 0 top
M1  Value*  [M-MARK1]  191.85 3.38 180 bottom
M2  Value*  [M-MARK1]  156.82 177.7 180 bottom
M3  Value*  [M-MARK1]  191.85 30.69 0 top
M4  Value*  [M-MARK1]  82.75 2.87 180 bottom
M5  Value*  [M-MARK1]  2.74 153.88 180 bottom
M6  Value*  [M-MARK1]  2.11 154 0 top
M7  Value*  [M-MARK1]  167.36 169.24 0 top
M8  Value*  [M-MARK1]  80.49 27.97 0 top
M41  U_MEM_SD_DDR5_X32#1  [BGA_0170_P080_140X120]  70.7 139.23 0 top
M42  U_MEM_SD_DDR5_X32#1  [BGA_0170_P080_140X120]  89.7 139.23 180 top
M43  U_MEM_SD_DDR5_X32#1  [BGA_0170_P080_140X120]  37.75 113.76 90 top
M44  U_MEM_SD_DDR5_X32#1  [BGA_0170_P080_140X120]  54.7 139.23 180 top
M45  U_MEM_SD_DDR5_X32#1  [BGA_0170_P080_140X120]  37.75 78.76 90 top
M46  U_MEM_SD_DDR5_X32#1  [BGA_0170_P080_140X120]  37.75 97.76 270 top
NOREF  -  []  46.03 -44.04 0 top
NOREF#2  -  [unnamed#2]  2.9 122.5 0 top
NOREF#3  -  []  189.78 128.5 0 top
NOREF#4  -  [unnamed#3]  68.01 112.08 180 bottom
NOREF#5  -  []  142.58 180.3 180 bottom
PJP5  -  [TOPSHORT_20X30]  194.26 99.24 180 top
PJP9  -  [TOPOPEN_20X79]  180.16 98.91 90 top
PJP10  -  [TOPOPEN_20X79]  13.41 90.25 180 bottom
PJP11  -  [TOPSHORT_20X30]  176.1 17.35 0 bottom
PJP12  -  [TOPOPEN_20X79]  182.32 5.67 270 top
PJP13  -  [TOPSHORT_20X30]  91.39 48.01 180 top
PJP14  -  [TOPOPEN_20X79]  82.37 45.16 90 top
PJP15  -  [TOPSHORT_20X30]  105.23 163.22 90 top
PJP16  -  [TOPOPEN_20X79]  93.32 160.1 180 top
PJP17  -  [TOPOPEN_20X79]  58.29 59.39 180 top
PJP18  -  [TOPOPEN_20X79]  128.09 165.2 270 top
PJP19  -  [TOPOPEN_20X79]  121.36 166.58 180 top
PJP20  -  [TOPOPEN_20X79]  146.25 170.31 270 top
PJP21  -  [TOPOPEN_20X79]  163.37 159.16 270 top
PJP22  -  [TOPOPEN_20X79]  135.53 165.18 270 top
PJP23  -  [TOPOPEN_20X79]  192.73 109.43 90 top
PJP24  -  [TOPOPEN_20X79]  143.81 165.2 270 top
PJP28  -  [TOPSHORT_20X30]  58.88 42.37 270 top
PJP34  -  [TOPSHORT_20X30]  187.76 111.71 270 bottom
PJP3210  -  [TOPSHORT_20X30]  190.45 151.84 180 top
PQ37  -  [PDFN5X6P_8_DUALMOS]  46.81 60.53 90 top
PQ40  -  [PDFN5X6P_8_DUALMOS]  16.18 141.84 180 top
PQ41  -  [PDFN5X6P_8_DUALMOS]  10.21 141.84 180 top
PQ42  -  [PDFN5X6P_8_DUALMOS]  10.21 127.18 0 top
PQ43  -  [PDFN5X6P_8_DUALMOS]  16.18 127.18 0 top
PQ44  -  [PDFN5X6P_8_DUALMOS]  8.2 77.68 0 top
PQ48  -  [PDFN5X6P_8_DUALMOS]  16.04 154.12 0 top
PQ49  -  [PDFN5X6P_8_DUALMOS]  10.21 154.13 0 top
PQ52  -  [PDFN5X6P_8_DUALMOS]  9.22 87.58 0 top
PQ53  -  [PDFN5X6P_8_DUALMOS]  3.38 87.58 0 top
PS1  -  [FUSE-0805]  60.53 171.66 270 top
Q1  -  [M-SOT23G]  192.48 138.64 0 top
Q2  Value*  [SOT363]  183.84 135.97 180 top
Q3  Value*  [SOT363]  189.56 138.51 180 top
Q4  Value*  [SOT363]  95.45 64.34 0 top
Q5  -  [M-SOT23G]  115.01 9.15 90 top
Q8  -  [PQFN8-PPS]  10.36 51.39 90 top
Q9  -  [PQFN8-PPS]  18.36 49.23 270 top
Q10  -  [PQFN8-PPS]  11 44.02 90 top
Q12  -  [M-SOT23G]  31.19 37.54 270 top
Q16  Value*  [SOT363]  170.1 23.68 270 top
Q19  -  [M-SOT23G]  86.94 52.4 180 top
Q20  -  [M-SOT23A]  90.12 58.12 90 top
Q27  -  [M-SOT23G]  69.42 163.4 180 top
Q30  -  [M-SOT23G]  179.02 159.59 90 top
Q37  -  [M-SOT23G]  54.18 172.8 0 top
Q41  VALUE  [PDFN-8P_B3X3_D65]  4.52 48.97 270 top
Q42  -  [M-SOT23G]  73.99 163.91 90 top
Q43  VALUE  [PDFN-8P_B3X3_D65]  4.52 52.4 270 top
Q44  Value*  [SOT363]  73.86 159.72 180 top
Q45  -  [M-SOT23A]  190.58 118.44 270 top
Q47  Value*  [SOT363]  184.48 159.97 0 top
Q48  -  [M-SOT23G]  162.76 11.26 90 top
Q49  -  [M-SOT23G]  186.89 165.92 180 top
Q50  -  [M-SOT23G]  179.02 162.89 90 top
Q51  -  [M-SOT23A]  95.71 27.38 90 top
Q53  -  [M-SOT23A]  54.43 167.72 180 top
Q54  -  [M-SOT23G]  179.02 166.2 90 top
Q55  -  [M-SOT23G]  120.34 168.99 180 bottom
Q57  -  [M-SOT23G]  75.51 167.97 90 top
Q58  Value*  [SOT363]  148.39 51.67 90 bottom
Q59  -  [M-SOT23G]  79.7 146.38 270 top
Q60  Value*  [SOT363]  128.98 7.45 90 top
Q62  -  [M-SOT23G]  42.49 123.52 90 top
Q63  -  [M-SOT23G]  165.18 23.32 180 top
Q64  -  [M-SOT23G]  31.32 88.6 0 top
Q66  -  [M-SOT23G]  171.65 10.37 270 top
Q67  -  [M-SOT23G]  71.83 37.8 90 top
Q68  -  [M-SOT23G]  104.34 44.53 0 top
Q69  -  [M-SOT23G]  107.95 3 270 bottom
Q70  -  [M-SOT23G]  111.61 3 270 bottom
Q71  -  [M-SOT23G]  104.42 3.58 270 bottom
Q78  -  [M-SOT23G]  107.01 65.36 180 top
Q86  -  [M-SOT23G]  60.78 166.07 0 top
Q88  Value*  [SOT363]  50.88 69.04 270 top
Q92  Value*  [SOT363]  100.66 60.02 90 top
Q96  -  [M-SOT353]  75.77 51.39 0 top
Q99  -  [M-SOT353]  107.39 70.69 0 top
Q100  Value*  [SOT363]  184.17 71.38 0 bottom
Q101  -  [M-SOT23G]  63.19 162.64 270 top
Q104  Value*  [SOT363]  95.83 61.29 90 top
Q105  -  [M-SOT23G]  95.2 20.27 270 top
Q106  -  [M-SOT23G]  183.87 74.7 90 bottom
Q109  Value*  [SOT363]  99.39 56.34 90 top
Q113  Value*  [SOT363]  66.62 163.53 180 top
Q114  Value*  [SOT363]  54.94 160.86 0 top
Q116  Value*  [SOT363]  187.15 159.97 0 top
Q119  Value*  [SOT363]  37.79 36.78 180 top
Q120  Value*  [SOT363]  43.76 160.35 270 bottom
Q122  Value*  [SOT363]  93.29 69.17 90 top
Q123  -  [M-SOT23G]  14.05 67.14 270 top
Q124  -  [M-SOT23G]  13.03 70.44 90 top
Q125  -  [M-SOT23G]  24.33 103.08 180 top
Q126  -  [M-SOT23G]  19.63 103.71 180 top
Q128  Value*  [SOT363]  92.91 64.21 0 top
Q129  -  [M-SOT23G]  3 111.46 270 top
Q130  Value*  [SOT363]  79.96 57.74 0 top
Q136  -  [M-SOT23G]  12.27 108.16 180 top
Q137  -  [M-SOT23G]  12.65 102.57 180 top
Q139  -  [M-SOT23G]  16.33 103.71 180 top
Q146  -  [M-SOT23G]  193.24 117.05 90 top
Q147  -  [M-SOT23G]  100.91 9.35 270 bottom
Q148  -  [M-SOT23G]  104.6 8.97 180 bottom
Q155  -  [M-SOT23G]  42.87 37.04 90 top
Q157  -  [M-SOT23G]  141.43 3 270 bottom
Q158  -  [M-SOT23G]  145.11 3 270 bottom
Q159  -  [M-SOT23G]  137.87 3 270 bottom
Q160  -  [M-SOT23G]  152.48 3 270 bottom
Q161  -  [M-SOT23G]  156.03 3 270 bottom
Q162  -  [M-SOT23G]  148.79 3 270 bottom
Q163  -  [M-SOT23G]  50.75 65.87 270 top
Q165  -  [M-SOT353]  8.46 113.11 90 top
Q182  -  [M-SOT23A]  25.73 162.39 90 top
Q183  -  [M-SOT23G]  115.65 167.85 180 bottom
Q188  -  [M-SOT23G]  88.98 156.92 180 bottom
Q190  -  [M-SOT23G]  172.67 156.16 90 top
R1  -  [M-R0402]  117.93 102.31 0 top
R2  -  [M-R0402]  127.48 99.31 180 top
R3  -  [M-R0603]  177.88 59.13 270 bottom
R4  -  [M-R0402]  127.48 100.2 180 top
R5  -  [M-R0402]  175.59 164.29 90 top
R6  -  [M-R0603]  167.46 59.01 270 bottom
R7  -  [M-R0402]  122.63 123.02 0 bottom
R8  -  [M-R0402]  167.97 127.08 180 top
R9  -  [M-R0402]  167.97 122 180 top
R10  -  [M-R0402]  172.41 158.83 90 top
R11  -  [M-R0402]  167.97 122.89 180 top
R12  -  [M-R0402]  167.97 118.19 180 top
R13  -  [M-R0402]  175.84 159.34 270 top
R14  -  [M-R0402]  167.97 116.41 180 top
R15  -  [M-R0402]  176.61 164.29 90 top
R16  -  [M-R0402]  118.82 170.77 90 bottom
R19  -  [M-R0402]  167.97 117.3 180 top
R20  -  [M-R0402]  131.01 111.51 180 bottom
R21  -  [M-R0402]  167.97 129.11 180 top
R22  -  [M-R0402]  167.97 115.52 180 top
R24  -  [M-R0402]  162.64 100.41 90 top
R25  -  [M-R0402]  167.97 124.41 0 top
R26  -  [M-R0402]  167.97 128.22 0 top
R27  -  [M-R0402]  167.97 126.19 0 top
R28  -  [M-R0402]  191.21 135.84 270 top
R29  -  [M-R0402]  192.73 141.3 90 top
R30  -  [M-R0402]  192.99 136.1 180 top
R31  -  [M-R0603]  183.34 167.08 0 top
R32  -  [M-R0402]  190.07 140.67 0 top
R33  -  [M-R0402]  185.5 135.46 90 top
R35  -  [M-R0603]  186.77 113.24 180 top
R36  -  [M-R0402]  182.7 138.13 180 top
R37  -  [M-R0402]  133.43 81.23 270 bottom
R38  -  [M-R0402]  134.31 81.23 90 bottom
R39  -  [M-R0402]  135.2 81.23 270 bottom
R40  -  [M-R0402]  132.03 81.66 0 bottom
R41  -  [M-R0402]  138.38 65.48 90 bottom
R42  -  [M-R0402]  133.81 65.48 270 bottom
R43  -  [M-R0402]  155.27 65.74 270 bottom
R44  -  [M-R0402]  136.6 65.48 90 bottom
R45  -  [M-R0402]  140.66 65.48 90 bottom
R46  -  [M-R0402]  167.97 121.11 0 top
R47  -  [M-R0402]  190.32 135.84 270 top
R48  -  [M-R0402]  141.05 132.26 270 bottom
R49  -  [M-R0402]  142.34 132.39 90 bottom
R50  -  [M-R0402]  144.42 133.53 0 bottom
R51  -  [M-R0402]  144.42 132.29 180 bottom
R52  -  [M-R0402]  122.76 126.06 0 bottom
R53  -  [M-R0402]  156.16 65.74 270 bottom
R54  -  [M-R0402]  117.42 133.43 0 bottom
R55  -  [M-R0402]  125.7 134.39 90 top
R56  -  [M-R0402]  126.59 134.39 270 top
R57  -  [M-R0402]  133.17 18.24 180 top
R58  -  [M-R0402]  133.17 19.13 180 top
R59  -  [M-R0402]  135.58 30.81 90 top
R60  -  [M-R0402]  136.22 19 0 top
R61  -  [M-R0402]  178.13 13.41 90 bottom
R62  -  [M-R0402]  87.45 47.07 270 top
R63  -  [M-R0402]  175.97 13.54 180 top
R64  -  [M-R0402]  90.25 48.21 90 top
R65  -  [M-R0402]  98.86 162.39 0 top
R66  -  [M-R0402]  180.54 17.05 180 top
R67  -  [M-R0402]  119.46 20.27 270 bottom
R68  -  [M-R0402]  178.13 15.19 90 bottom
R69  -  [M-R0402]  190.58 96.09 0 bottom
R70  -  [M-R0402]  98.88 164.54 180 top
R71  -  [M-R0402]  136.47 30.81 90 top
R72  -  [M-R0402]  126.06 20.78 90 bottom
R73  -  [M-R0402]  133.04 31.45 0 top
R74  -  [M-R0402]  133.17 17.35 180 top
R75  -  [M-R0402]  128.09 20.15 180 bottom
R76  -  [M-R0402]  133.04 32.34 0 top
R77  -  [M-R0402]  128.85 23.32 180 bottom
R78  -  [M-R0402]  105.99 37.29 270 bottom
R79  -  [M-R0402]  128.85 22.43 180 bottom
R80  -  [M-R0402]  130.38 16.21 180 bottom
R81  -  [M-R0402]  122.76 24.59 0 bottom
R82  -  [M-R0402]  124.66 11.38 90 top
R83  -  [M-R0402]  107.77 37.54 270 bottom
R84  -  [M-R0402]  106.88 37.54 270 bottom
R85  -  [M-R0402]  130.38 17.86 180 bottom
R86  -  [M-R0402]  128.85 24.21 180 bottom
R87  -  [M-R0402]  88.34 47.07 90 top
R88  -  [M-R0402]  123.14 21.54 270 bottom
R89  -  [M-R0402]  122.25 21.54 270 bottom
R91  -  [M-R0402]  109.55 27.64 270 bottom
R92  -  [M-R0402]  132.41 22.3 0 bottom
R93  -  [M-R0402]  63.75 63.71 180 top
R94  -  [M-R0402]  102.44 27.38 0 top
R95  -  [M-R0402]  95.83 23.45 180 top
R96  -  [M-R0402]  95.83 24.34 0 top
R97  -  [M-R0402]  29.41 64.21 180 top
R98  -  [M-R0402]  117.68 122.51 0 bottom
R99  -  [M-R0402]  18.74 120.09 270 top
R100  -  [M-R0402]  132.41 24.97 0 bottom
R101  -  [M-R0402]  29.41 63.33 0 top
R102  -  [M-R0402]  132.41 21.42 0 bottom
R103  -  [M-R0402]  144.22 23.19 0 bottom
R104  -  [M-R0402]  98.5 49.86 0 top
R105  -  [M-R0402]  144.22 24.08 180 bottom
R107  -  [M-R0402]  127.96 21.54 0 bottom
R109  -  [M-R0402]  132.41 24.08 0 bottom
R110  -  [M-R0402]  110.95 10.24 90 top
R111  -  [M-R0402]  127.58 11.38 270 top
R112  -  [M-R0402]  116.79 12.4 90 top
R113  -  [M-R0402]  181.96 22.48 0 top
R114  -  [M-R0402]  165.56 13.8 270 bottom
R116  -  [M-R0402]  152.73 25.23 90 top
R117  -  [M-R0402]  29.41 60.61 180 top
R118  -  [M-R0402]  167.97 21.42 0 bottom
R119  -  [M-R0402]  31.19 60.28 180 top
R121  -  [M-R0402]  30.17 56.98 90 top
R122  -  [M-R0402]  118.82 6.56 270 top
R123  -  [M-R0402]  29.29 56.98 270 top
R124  -  [M-R0402]  4.77 107.52 180 top
R125  -  [M-R0402]  121.49 6.56 270 top
R126  -  [M-R0402]  166.06 11.89 0 bottom
R127  -  [M-R0402]  2.87 103.58 90 top
R128  -  [M-R0402]  2.36 107.52 180 top
R131  -  [M-R0402]  122.38 6.56 270 top
R132  -  [M-R0402]  65.4 123.57 0 bottom
R133  -  [M-R0402]  182.62 27.13 90 top
R134  -  [M-R0402]  186.18 103.86 270 top
R135  -  [M-R0402]  117.68 12.4 270 top
R136  -  [M-R0402]  119.58 12.4 90 bottom
R137  -  [M-R0402]  115.9 12.4 90 bottom
R138  -  [M-R0402]  177.49 23.7 180 top
R139  -  [M-R0402]  117.88 6.56 270 top
R140  -  [M-R0402]  165.3 19.89 90 top
R141  -  [M-R0402]  165.81 19.64 0 bottom
R142  -  [M-R0402]  177.49 24.59 180 top
R143  -  [M-R0402]  144.22 21.8 180 bottom
R144  -  [M-R0402]  127.84 9.35 180 top
R145  -  [M-R0402]  131.14 9.22 90 top
R146  -  [M-R0402]  132.41 23.19 0 bottom
R148  -  [M-R0402]  117.93 103.2 0 top
R149  -  [M-R0402]  177.49 21.39 180 top
R150  -  [M-R0402]  75.26 157.31 180 top
R151  -  [M-R0402]  184.99 107.65 90 bottom
R153  -  [M-R0402]  117 6.56 270 top
R155  -  [M-R0402]  119.71 6.56 270 top
R156  -  [M-R0402]  190.47 101.88 180 top
R157  -  [M-R0402]  120.6 6.56 90 top
R158  -  [M-R0402]  165.68 25.61 180 top
R163  -  [M-R0402]  187.02 102.95 90 top
R164  -  [M-R0402]  181.96 21.59 180 top
R165  -  [M-R0402]  91.39 91.77 180 bottom
R166  -  [M-R0402]  102.95 22.56 0 top
R167  -  [M-R0402]  108.56 82.48 0 top
R168  -  [M-R0402]  144.73 28.4 180 top
R169  -  [M-R0402]  108.56 81.56 180 top
R170  -  [M-R0402]  144.22 14.05 180 bottom
R171  -  [M-R0402]  146.89 19.26 0 top
R172  -  [M-R0402]  190.45 104.09 0 top
R173  -  [M-R0402]  137.11 76.91 0 bottom
R174  -  [M-R0402]  160.98 10.62 270 bottom
R175  -  [M-R0402]  108.53 84.33 180 top
R176  -  [M-R0402]  109.3 10.24 90 top
R177  -  [M-R0402]  2.49 72.09 0 top
R178  -  [M-R0402]  82.63 56.47 0 top
R179  -  [M-R0402]  189.49 112.2 90 top
R180  -  [M-R0402]  108.53 83.39 0 top
R181  -  [M-R0402]  2.36 73.99 0 top
R182  -  [M-R0402]  2.49 65.1 90 top
R183  -  [M-R0402]  103.33 55.32 0 top
R184  -  [M-R0402]  103.33 56.21 180 top
R185  -  [M-R0402]  1.6 65.1 90 top
R186  -  [M-R0402]  39.7 36.78 90 top
R187  -  [M-R0402]  35.12 37.68 90 top
R188  -  [M-R0402]  103.33 57.1 180 top
R189  -  [M-R0603]  170.13 18.11 0 top
R190  -  [M-R0603]  169.37 12.65 270 bottom
R191  -  [M-R0402]  34.24 35.9 270 top
R192  -  [M-R0402]  161.11 31.07 90 bottom
R193  -  [M-R0402]  65.53 58.12 0 top
R194  -  [M-R0402]  34.23 37.68 270 top
R195  -  [M-R0402]  103.33 57.99 0 top
R196  -  [M-R0402]  35.14 35.9 270 top
R197  -  [M-R0402]  161.24 112.47 0 bottom
R198  -  [M-R0402]  167.97 125.3 0 top
R199  -  [M-R0402]  188.04 162.89 90 top
R200  -  [M-R0402]  9.09 64.98 270 top
R201  -  [M-R0402]  10.24 67.8 0 top
R202  -  [M-R0402]  91.26 95.84 180 bottom
R203  -  [M-R0402]  185.37 162.89 270 top
R204  -  [M-R0402]  4.65 62.56 90 top
R205  -  [M-R0402]  137.11 77.8 180 bottom
R206  -  [M-R0402]  148.03 80.85 270 bottom
R207  -  [M-R0402]  148.03 68.41 270 bottom
R208  -  [M-R0402]  5.54 62.56 90 top
R211  -  [M-R0402]  134.7 65.48 270 bottom
R213  -  [M-R0603]  98.58 47.32 270 top
R214  -  [M-R0603]  191.97 158.19 90 top
R215  -  [M-R0402]  82.63 55.58 180 top
R216  -  [M-R0402]  182.83 159.46 270 top
R217  -  [M-R0402]  187.15 162.89 270 top
R218  -  [M-R0402]  187.53 157.69 0 top
R219  -  [M-R0402]  63.75 58.12 0 top
R220  -  [M-R0402]  187.91 99.27 0 top
R221  -  [M-R0402]  189.69 99.27 0 top
R222  -  [M-R0402]  181.3 163.02 90 top
R223  -  [M-R0402]  193.83 94.41 180 top
R224  -  [M-R0402]  187.73 97.23 0 top
R225  -  [M-R0402]  191.87 97.87 90 top
R226  -  [M-R0603]  97.1 45.16 0 top
R227  -  [M-R0402]  135.58 65.48 90 bottom
R228  -  [M-R0402]  189.74 97.89 270 top
R230  -  [M-R0603]  16.23 141.63 270 bottom
R232  -  [M-R0603]  14.3 117.55 180 top
R235  -  [M-R0402]  156.03 9.6 180 top
R236  -  [M-R0402]  165.81 20.53 0 bottom
R239  -  [M-R0603]  23.95 117.94 0 top
R241  -  [M-R0402]  3.76 72.22 90 top
R242  -  [M-R0603]  25.22 149.18 90 bottom
R245  -  [M-R0402]  181.3 166.96 90 top
R246  -  [M-R0402]  161.87 10.62 90 bottom
R247  -  [M-R0402]  16.18 139.42 270 bottom
R248  -  [M-R0402]  189.18 158.7 90 top
R249  -  [M-R0402]  126.95 16.34 180 bottom
R250  -  [M-R0402]  161.62 149.56 180 bottom
R251  -  [M-R0402]  160.22 31.07 270 bottom
R252  -  [M-R0402]  3.76 73.99 270 top
R253  -  [M-R0402]  108.03 6.05 90 bottom
R254  -  [M-R0402]  192.61 148.03 180 top
R255  -  [M-R0402]  93.93 56.59 0 top
R256  -  [M-R0402]  91.13 55.96 180 top
R257  -  [M-R0402]  89.23 55.96 0 top
R258  -  [M-R0402]  110.44 9.73 180 bottom
R259  -  [M-R0402]  55.32 170.26 180 top
R260  -  [M-R0402]  99.9 51.13 90 top
R262  -  [M-R0402]  117.93 130.89 180 top
R264  -  [M-R0402]  99.01 58.12 0 top
R266  -  [M-R0402]  101.55 55.71 90 top
R269  -  [M-R0402]  176.1 22.3 90 top
R271  -  [M-R0402]  111.84 10.24 90 top
R273  -  [M-R0402]  122.12 19.26 270 bottom
R278  -  [M-R0402]  18.87 149.05 0 bottom
R280  -  [M-R0603]  17.73 147.78 180 bottom
R281  -  [M-R0402]  82.37 8.33 0 bottom
R283  -  [M-R0402]  1.85 67.39 90 top
R284  -  [M-R0402]  112.67 9.43 270 top
R285  -  [M-R0402]  134.06 14.18 180 top
R286  -  [M-R0402]  115.9 12.4 90 top
R287  -  [M-R0402]  118.57 12.4 270 top
R288  -  [M-R0402]  126.69 11.38 90 top
R289  -  [M-R0402]  102.95 21.67 0 top
R290  -  [M-R0402]  134.06 11.51 0 top
R291  -  [M-R0402]  102.44 26.5 180 top
R292  -  [M-R0402]  102.44 24.72 180 top
R293  -  [M-R0402]  100.91 20.96 0 top
R294  -  [M-R0402]  100.91 20.07 180 top
R295  -  [M-R0402]  112.47 12.4 90 top
R296  -  [M-R0402]  115.14 7.12 180 top
R297  -  [M-R0402]  183.59 157.69 180 top
R298  -  [M-R0402]  102.44 25.61 180 top
R299  -  [M-R0402]  134.06 12.4 180 top
R300  -  [M-R0402]  121.36 12.4 90 top
R301  -  [M-R0402]  138.51 11.51 0 top
R302  -  [M-R0402]  140.41 11.51 180 top
R303  -  [M-R0402]  1.85 69.17 270 top
R304  -  [M-R0402]  6.04 63.96 180 top
R305  -  [M-R0402]  188.16 119.08 270 top
R306  -  [M-R0402]  4.14 63.96 0 top
R307  -  [M-R0402]  57.1 170.26 180 top
R308  -  [M-R0402]  17.86 120.09 90 top
R309  -  [M-R0402]  120.47 12.4 90 top
R310  -  [M-R0603]  116.03 145.24 90 bottom
R311  -  [M-R0402]  134.06 13.29 180 top
R312  -  [M-R0402]  89.99 50.56 0 top
R313  -  [M-R0402]  167.33 8.59 90 top
R314  -  [M-R0402]  116.79 12.4 90 bottom
R315  -  [M-R0402]  177.49 22.81 0 top
R316  -  [M-R0402]  181.56 157.31 90 top
R317  -  [M-R0402]  52.4 54.56 180 bottom
R319  -  [M-R0402]  56.08 53.55 0 top
R320  -  [M-R0402]  52.4 55.45 180 bottom
R321  -  [M-R0402]  123.27 11.26 180 top
R322  -  [M-R0603]  93.42 40.97 90 top
R323  -  [M-R0402]  124.41 16.08 270 bottom
R325  -  [M-R0402]  45.92 157.56 180 bottom
R326  -  [M-R0402]  52.4 54.56 180 top
R327  -  [M-R0402]  141.17 5.79 270 top
R329  -  [M-R0402]  142.32 5.79 270 top
R334  -  [M-R0402]  121.87 16.46 270 bottom
R335  -  [M-R0402]  179.4 40.59 270 top
R336  -  [M-R0402]  133.04 33.23 0 top
R337  -  [M-R0402]  54.3 53.55 180 top
R338  -  [M-R0402]  122.88 12.4 270 bottom
R339  -  [M-R0402]  123.77 12.4 270 bottom
R340  -  [M-R0402]  102.82 28.65 90 top
R341  -  [M-R0402]  120.73 20.4 90 bottom
R342  -  [M-R0402]  156.29 40.59 270 top
R343  -  [M-R0402]  120.67 22.84 180 bottom
R344  -  [M-R1206]  37.41 54.69 0 top
R345  -  [M-R1206]  10.74 58.25 270 top
R346  -  [M-R1206]  7.44 117.68 270 top
R347  -  [M-R0402]  41.86 161.98 180 bottom
R348  -  [M-R0402]  57.86 53.55 180 top
R349  -  [M-R0402]  105.74 30.94 90 bottom
R350  -  [M-R0402]  132.41 25.86 180 bottom
R351  VALUE*  [M-R0805]  56.34 70.31 270 top
R352  -  [M-R0402]  106.63 30.43 90 bottom
R353  -  [M-R0402]  135.84 15.83 270 top
R354  -  [M-R0402]  109.04 15.34 0 bottom
R355  -  [M-R0402]  108.41 19.13 0 bottom
R356  -  [M-R0402]  88.34 8.97 180 bottom
R357  -  [M-R0402]  71.96 35.64 0 top
R358  -  [M-R0402]  109.07 14.46 0 bottom
R359  -  [M-R0402]  185.37 157.69 180 top
R360  -  [M-R0402]  101.42 14.3 90 top
R361  -  [M-R0402]  120.47 12.4 90 bottom
R362  -  [M-R0402]  88.34 9.86 180 bottom
R363  -  [M-R0402]  115.65 15.7 270 bottom
R364  VALUE*  [M-R0805]  58.62 70.31 270 top
R365  -  [M-R0402]  81.51 51.01 90 top
R366  -  [M-R0402]  112.8 37.54 270 bottom
R367  -  [M-R0402]  100.91 18.39 180 top
R368  -  [M-R0402]  100.91 19.26 0 top
R369  -  [M-R0402]  115.65 19.76 180 bottom
R370  -  [M-R0402]  134.06 35.64 180 top
R371  -  [M-R0402]  66.5 155.4 90 bottom
R372  -  [M-R0603]  134.31 36.78 180 top
R373  -  [M-R0402]  75.64 161.12 270 top
R374  -  [M-R0603]  108.79 20.4 180 bottom
R375  -  [M-R0402]  103.45 31.96 0 bottom
R376  -  [M-R0603]  114.04 25 270 bottom
R377  -  [M-R0402]  134.06 34.12 0 top
R378  -  [M-R0402]  105.1 37.29 270 bottom
R379  -  [M-R0402]  130.5 11 180 top
R380  VALUE*  [M-R0805]  60.91 70.31 270 top
R381  VALUE*  [M-R0805]  63.19 70.31 270 top
R382  VALUE*  [M-R0805]  65.48 70.31 270 top
R383  -  [M-R0402]  109.68 22.43 180 bottom
R384  -  [M-R0402]  147.94 176.2 270 bottom
R385  -  [M-R0402]  147.05 176.2 270 bottom
R386  -  [M-R0402]  152.6 174.81 270 top
R387  -  [M-R1206]  3.38 58.12 270 top
R388  -  [M-R0402]  153.49 174.81 270 top
R389  -  [M-R0402]  113.11 15.83 0 bottom
R390  VALUE*  [M-R0805]  67.77 70.31 270 top
R392  -  [M-R0402]  151.71 174.81 270 top
R393  -  [M-R0402]  43.89 163.53 270 bottom
R394  -  [M-R0402]  149.94 174.81 270 top
R398  -  [M-R0402]  100.53 75.26 0 top
R403  -  [M-R0402]  44.78 163.53 270 bottom
R404  -  [M-R0402]  76.28 163.02 90 top
R405  -  [M-R0402]  76.28 164.8 270 top
R408  -  [M-R0402]  69.93 170.89 180 top
R409  -  [M-R0603]  90.12 62.18 90 top
R412  -  [M-R0402]  42.62 167.59 270 top
R413  -  [M-R0402]  150.82 174.81 270 top
R414  -  [M-R0402]  149.81 176.2 270 bottom
R415  -  [M-R0402]  148.92 176.2 270 bottom
R416  -  [M-R0402]  154.41 174.81 270 top
R417  -  [M-R0402]  155.29 174.81 270 top
R418  -  [M-R0402]  67.51 170.01 180 top
R419  -  [M-R0402]  149.05 174.81 270 top
R420  -  [M-R0402]  44.53 157.94 90 bottom
R422  -  [M-R0603]  13.94 75.77 90 top
